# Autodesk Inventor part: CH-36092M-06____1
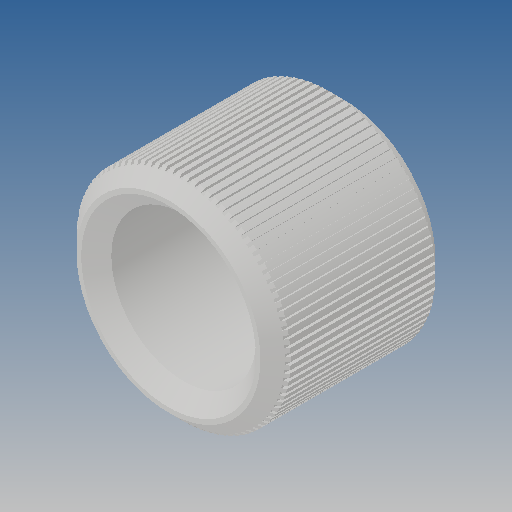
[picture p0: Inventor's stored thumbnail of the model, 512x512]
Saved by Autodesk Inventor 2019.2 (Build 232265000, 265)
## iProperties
Created: 2012-09
Part Number: CH-36092M-06____1
Material: Ogólny
Document SubType Name: Modeling
Designer: CADENGINEERING4
Density: 1 g/cm^3
Appearance: Domyślna
Author: CADENGINEERING4
Revision Number: ÈÎºÎ
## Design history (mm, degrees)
feature "NONE"
node "Bryła1"
